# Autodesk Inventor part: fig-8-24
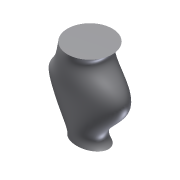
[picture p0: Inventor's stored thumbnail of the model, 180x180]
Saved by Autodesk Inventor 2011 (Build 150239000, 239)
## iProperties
Shininess: 64.0
Length Units: 11269
Angle Units: 11279
Time Units: 11290
Mass Units: 11283
Length Display Precision: 3
Angle Display Precision: 2
Compacted: True
Part Number: fig-8-24
Document SubType Name: Modeling
Created: 2002-12
Designer: deepak
Density: 1 g/cm^3
Density: 0.0
Volumn: 0.0
Area: 0.0
PropertySet Name: Model Information
Control State: 0
Master: False
Checked Out: False
Author: deepak
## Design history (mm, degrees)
sketch "Sketch1"
  geometry: 2 further points; 1 other entity
  constraints: 1 coincident, 3 other
workplane "Work Plane1"
workplane "Work Plane2"
sketch "Sketch3"
  geometry: C1 r 60 at (0, 0); 1 further point
  constraints: 1 centre point, 1 coincident, 1 other
sketch "Sketch4"
  geometry: 8 further points
  constraints: 8 other
sketch "Sketch5"
  geometry: 6 further points
  constraints: 6 other
sketch "Sketch6"
  geometry: 6 further points
  constraints: 6 other
  dimensions: "d20" = 35 distance of point (0, 0) point (-35, 0); "d21" = 0 vertical distance of point (0, 0) point (-35, 0); "d22" = 225 vertical distance of point (0, 0) point (-60, 225); "d23" = 60 horizontal distance of point (0, 0) point (-60, 225); "d24" = 100 horizontal distance of point (0, 0) point (-100, 125); "d25" = 125 vertical distance of point (0, 0) point (-100, 125)
loft "Loft5" dims "d54" = 0, "d55" = 90 deg, "d56" = 0, "d57" = 90 deg, "d58" = 0, "d59" = 90 deg, "d60" = 0, "d61" = 90 deg
body "Solid2"
other parameters: "d5" = 125
